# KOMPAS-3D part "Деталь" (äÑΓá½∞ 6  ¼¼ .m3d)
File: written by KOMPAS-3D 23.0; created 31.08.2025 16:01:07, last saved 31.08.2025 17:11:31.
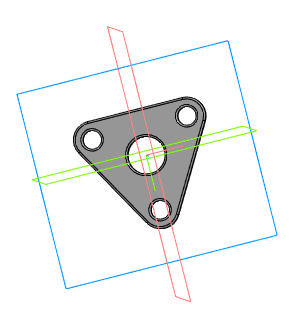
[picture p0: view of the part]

Document properties: Автор: PC; Полное имя файла: C:\Users\PC\Desktop\3D\Трыугольник\Деталь 6  мм .m3d

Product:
- Part/product: Деталь
    Материал: Полипропилен ГОСТ 26996-86 (density 900 kg/m3)
    Масса: 0.013312

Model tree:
1. Эскиз:1
2. Элемент выдавливания:1
     Расстояние 1 = 6
3. Скругление:1  (with: Элемент выдавливания:1)
     Радиус = 1
4. Скругление:2  (with: Элемент выдавливания:1)
     Радиус = 1
5. Скругление:3  (with: Элемент выдавливания:1)  (labels: Полипропилен ГОСТ 26996-86)
     Радиус = 1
